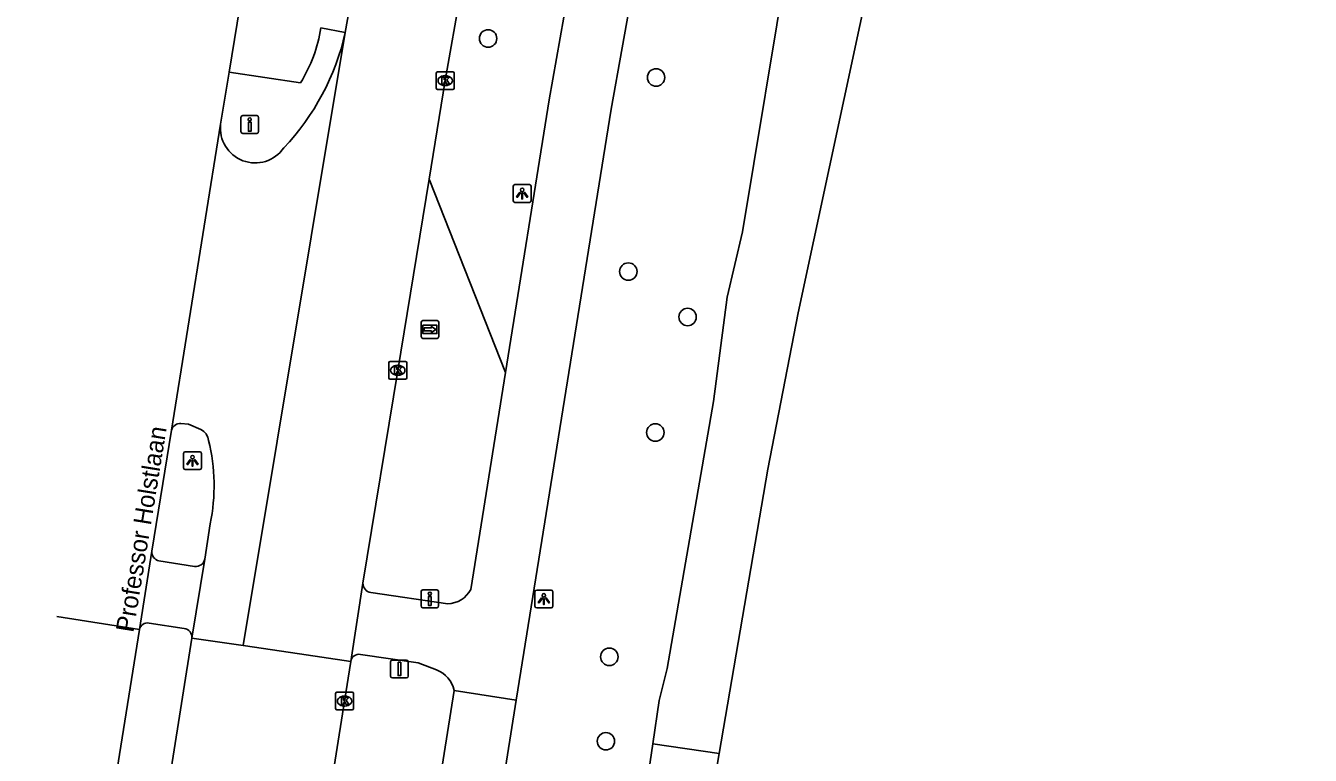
# Model space of a CAD drawing. Extents: x 160203 to 161526, y 379529 to 381797.
# Drawn here: x 160352.7 to 160424.8, y 380603.3 to 380644.2 of the extents above; entities that cross this region are included whole.
import ezdxf

# ---------------------------------------------------------------- set-up
doc = ezdxf.new("R2010")
doc.units = 0
for name, color, linetype in [('IMGEO_Berm_groen', 7, 'Continuous'), ('IMGEO_Boom', 7, 'Continuous'), ('IMGEO_Drukknoppaal', 7, 'Continuous'), ('IMGEO_Fietspad_gesloten', 7, 'Continuous'), ('IMGEO_Fietspad_open', 7, 'Continuous'), ('IMGEO_Grasland_agrarisch', 7, 'Continuous'), ('IMGEO_Kolk', 7, 'Continuous'), ('IMGEO_Lichtpunt', 7, 'Continuous'), ('IMGEO_Openbare_ruimte_label', 7, 'Continuous'), ('IMGEO_Rijbaan_regionaal_gesloten', 7, 'Continuous'), ('IMGEO_Verkeersbordpaal', 7, 'Continuous'), ('IMGEO_Verkeerseiland_open', 7, 'Continuous'), ('IMGEO_Waterloop', 7, 'Continuous'), ('IMGEO_Wegwijzer', 7, 'Continuous')]:
    doc.layers.add(name, color=color, linetype=linetype)

msp = doc.modelspace()

# ---------------------------------------------------------------- linework, layer by layer
at = {"layer": 'IMGEO_Berm_groen'}
for points in [[(160375.315, 380635.633), (160379.602, 380624.787)], [(160352.684, 380385.815), (160356.287, 380408.516), (160361.612, 380442.808), (160363.62, 380454.848), (160364.253, 380457.684), (160365.385, 380465.491), (160366.679, 380472.607), (160367.782, 380480.751), (160370.802, 380500), (160371.249, 380502.852), (160372.818, 380512.852), (160374.702, 380524.857), (160374.72, 380524.951), (160376.133, 380532.248), (160378.196, 380546.027), (160380.328, 380558.075), (160380.897, 380562.583), (160383.168, 380574.421), (160385.043, 380587.001), (160386.211, 380592.747), (160387.862, 380603.942)]]:
    msp.add_lwpolyline(points, dxfattribs=at)
at = {"layer": 'IMGEO_Boom'}
for centre in [(160378.626, 380643.518), (160388.05, 380641.33), (160386.493, 380630.443), (160389.817, 380627.893), (160388.006, 380621.413), (160385.426, 380608.831), (160385.234, 380604.095)]:
    msp.add_circle(centre, 0.489, dxfattribs=at)
at = {"layer": 'IMGEO_Drukknoppaal'}
for p, q in [((160364.857, 380639.19), (160365.647, 380639.19)), ((160365.647, 380639.19), (160364.857, 380639.19)), ((160364.757, 380638.29), (160364.757, 380639.09)), ((160364.757, 380639.09), (160364.757, 380638.29)), ((160365.747, 380639.09), (160365.747, 380638.29)), ((160365.747, 380638.29), (160365.747, 380639.09)), ((160365.647, 380638.19), (160364.857, 380638.19)), ((160364.857, 380638.19), (160365.647, 380638.19)), ((160374.961, 380612.585), (160375.751, 380612.585)), ((160375.751, 380612.585), (160374.961, 380612.585)), ((160374.861, 380611.685), (160374.861, 380612.485)), ((160374.861, 380612.485), (160374.861, 380611.685)), ((160375.851, 380612.485), (160375.851, 380611.685)), ((160375.851, 380611.685), (160375.851, 380612.485)), ((160375.751, 380611.585), (160374.961, 380611.585)), ((160374.961, 380611.585), (160375.751, 380611.585))]:
    msp.add_line(p, q, dxfattribs=at)
for points in [[(160365.327, 380638.815), (160365.327, 380638.315), (160365.177, 380638.315), (160365.177, 380638.815), (160365.327, 380638.815)], [(160375.431, 380612.21), (160375.431, 380611.71), (160375.281, 380611.71), (160375.281, 380612.21), (160375.431, 380612.21)]]:
    msp.add_lwpolyline(points, dxfattribs=at)
for centre in [(160365.252, 380638.98), (160375.356, 380612.375)]:
    msp.add_circle(centre, 0.085, dxfattribs=at)
for centre, start, end in [((160364.857, 380639.09), 90, 180), ((160364.857, 380639.09), 90, 180), ((160365.647, 380639.09), 0, 90), ((160365.647, 380639.09), 360, 90), ((160364.857, 380638.29), 180, 270), ((160364.857, 380638.29), 180, 270), ((160365.647, 380638.29), 270, 0), ((160365.647, 380638.29), 270, 0), ((160374.961, 380612.485), 90, 180), ((160374.961, 380612.485), 90, 180), ((160375.751, 380612.485), 0, 90), ((160375.751, 380612.485), 360, 90), ((160374.961, 380611.685), 180, 270), ((160374.961, 380611.685), 180, 270), ((160375.751, 380611.685), 270, 0), ((160375.751, 380611.685), 270, 0)]:
    msp.add_arc(centre, 0.1, start, end, dxfattribs=at)
at = {"layer": 'IMGEO_Fietspad_gesloten'}
for points in [[(160383.286, 380647.043), (160382.053, 380640.078), (160379.602, 380624.787)], [(160386.76, 380646.455), (160385.522, 380639.561), (160380.205, 380606.406)], [(160379.602, 380624.787), (160377.651, 380612.613)], [(160376.36, 380611.804), (160372.039, 380612.43)], [(160371.472, 380608.969), (160374.693, 380608.486), (160375.736, 380608.096)], [(160376.723, 380606.946), (160374.855, 380595.163)], [(160376.723, 380606.946), (160380.205, 380606.406)], [(160380.205, 380606.406), (160371.189, 380549.526), (160367.433, 380526.109), (160363.246, 380500), (160361.784, 380490.887), (160355.339, 380450.611)]]:
    msp.add_lwpolyline(points, dxfattribs=at)
for centre, radius, start, end in [((160372.143, 380612.961), 0.541, 179.27552, 258.89616), ((160376.321, 380613.301), 1.497, 271.49548, 332.65082), ((160371.397, 380608.49), 0.484, 81.13593, 170.17472), ((160375.175, 380606.616), 1.582, 12.026, 69.2504)]:
    msp.add_arc(centre, radius, start, end, dxfattribs=at)
at = {"layer": 'IMGEO_Fietspad_open'}
for points in [[(160360.16, 380614.208), (160362.159, 380613.9)], [(160361.581, 380610.416), (160359.604, 380610.72)]]:
    msp.add_lwpolyline(points, dxfattribs=at)
for centre, radius, start, end in [((160360.28, 380614.709), 0.515, 174.62319, 256.57055), ((160362.219, 380614.429), 0.532, 263.57434, 346.42303), ((160359.517, 380610.264), 0.464, 79.16832, 167.47411), ((160361.54, 380609.952), 0.466, 351.66885, 84.91148)]:
    msp.add_arc(centre, radius, start, end, dxfattribs=at)
at = {"layer": 'IMGEO_Grasland_agrarisch'}
msp.add_lwpolyline([(160391.591, 380603.409), (160387.523, 380579.574), (160379.296, 380526.737), (160378.851, 380524.294), (160377.634, 380517.623), (160376.818, 380512.224), (160375.308, 380502.238), (160374.97, 380500), (160372.848, 380488.626), (160370.146, 380472.104), (160369.369, 380465.742), (160366.989, 380450.176), (160364.586, 380436.343), (160363.043, 380425.732), (160361.825, 380419.072), (160360.362, 380409.1), (160358.765, 380400.008), (160356.87, 380389.591), (160356.183, 380385.289)], dxfattribs=at)
at = {"layer": 'IMGEO_Kolk'}
for p, q in [((160375.717, 380640.726), (160375.717, 380641.578)), ((160375.792, 380641.652), (160376.644, 380641.652)), ((160376.205, 380641.432), (160376.23, 380641.432)), ((160376.718, 380641.578), (160376.718, 380640.726)), ((160376.644, 380640.652), (160375.792, 380640.652)), ((160376.228, 380640.872), (160376.203, 380640.872)), ((160373.059, 380624.476), (160373.059, 380625.328)), ((160373.134, 380625.402), (160373.986, 380625.402)), ((160373.547, 380625.182), (160373.572, 380625.182)), ((160374.06, 380625.328), (160374.06, 380624.476)), ((160373.986, 380624.402), (160373.134, 380624.402)), ((160373.57, 380624.622), (160373.545, 380624.622)), ((160370.072, 380605.922), (160370.072, 380606.774)), ((160370.147, 380606.848), (160370.999, 380606.848)), ((160371.073, 380606.774), (160371.073, 380605.922)), ((160370.583, 380606.068), (160370.558, 380606.068)), ((160370.56, 380606.628), (160370.585, 380606.628)), ((160370.999, 380605.848), (160370.147, 380605.848))]:
    msp.add_line(p, q, dxfattribs=at)
for points in [[(160375.717, 380640.726), (160375.717, 380641.578)], [(160375.792, 380641.652), (160376.644, 380641.652)], [(160376.038, 380641.352), (160376.161, 380641.352), (160376.161, 380641.201), (160376.291, 380641.352), (160376.455, 380641.352), (160376.309, 380641.201), (160376.462, 380640.952), (160376.31, 380640.952), (160376.225, 380641.116), (160376.161, 380641.049), (160376.161, 380640.952), (160376.038, 380640.952), (160376.038, 380641.352)], [(160376.718, 380641.578), (160376.718, 380640.726)], [(160376.644, 380640.652), (160375.792, 380640.652)], [(160373.059, 380624.476), (160373.059, 380625.328)], [(160373.134, 380625.402), (160373.986, 380625.402)], [(160373.38, 380625.102), (160373.503, 380625.102), (160373.503, 380624.951), (160373.633, 380625.102), (160373.797, 380625.102), (160373.651, 380624.951), (160373.804, 380624.702), (160373.652, 380624.702), (160373.567, 380624.866), (160373.503, 380624.799), (160373.503, 380624.702), (160373.38, 380624.702), (160373.38, 380625.102)], [(160374.06, 380625.328), (160374.06, 380624.476)], [(160373.986, 380624.402), (160373.134, 380624.402)], [(160370.072, 380605.922), (160370.072, 380606.774)], [(160370.147, 380606.848), (160370.999, 380606.848)], [(160371.073, 380606.774), (160371.073, 380605.922)], [(160370.393, 380606.548), (160370.516, 380606.548), (160370.516, 380606.397), (160370.646, 380606.548), (160370.81, 380606.548), (160370.664, 380606.397), (160370.817, 380606.148), (160370.665, 380606.148), (160370.58, 380606.312), (160370.516, 380606.245), (160370.516, 380606.148), (160370.393, 380606.148), (160370.393, 380606.548)], [(160370.999, 380605.848), (160370.147, 380605.848)]]:
    msp.add_lwpolyline(points, dxfattribs=at)
for centre, start, end in [((160375.794, 380641.576), 91.55205, 178.44795), ((160375.794, 380641.576), 91.55205, 178.44795), ((160376.642, 380641.576), 1.55205, 88.44795), ((160376.642, 380641.576), 1.55205, 88.44795), ((160375.794, 380640.728), 181.55205, 268.44795), ((160375.794, 380640.728), 181.55205, 268.44795), ((160376.642, 380640.728), 271.55205, 358.44795), ((160376.642, 380640.728), 271.55205, 358.44795), ((160373.136, 380625.326), 91.55205, 178.44795), ((160373.136, 380625.326), 91.55205, 178.44795), ((160373.984, 380625.326), 1.55205, 88.44795), ((160373.984, 380625.326), 1.55205, 88.44795), ((160373.136, 380624.478), 181.55205, 268.44795), ((160373.136, 380624.478), 181.55205, 268.44795), ((160373.984, 380624.478), 271.55205, 358.44795), ((160373.984, 380624.478), 271.55205, 358.44795), ((160370.149, 380606.772), 91.55205, 178.44795), ((160370.149, 380606.772), 91.55205, 178.44795), ((160370.997, 380606.772), 1.55205, 88.44795), ((160370.997, 380606.772), 1.55205, 88.44795), ((160370.149, 380605.924), 181.55205, 268.44795), ((160370.149, 380605.924), 181.55205, 268.44795), ((160370.997, 380605.924), 271.55205, 358.44795), ((160370.997, 380605.924), 271.55205, 358.44795)]:
    msp.add_arc(centre, 0.0765, start, end, dxfattribs=at)
for centre, major_axis, ratio, start_param, end_param in [((160376.204, 380641.152), (-0.387, 0.002), 0.722429, 4.712389, 7.853982), ((160376.229, 380641.152), (-0.39, 0.002), 0.717154, 1.570796, 4.712389), ((160373.546, 380624.902), (-0.387, 0.002), 0.722429, 4.712389, 7.853982), ((160373.571, 380624.902), (-0.39, 0.002), 0.717154, 1.570796, 4.712389), ((160370.559, 380606.348), (-0.387, 0.002), 0.722429, 4.712389, 7.853982), ((160370.584, 380606.348), (-0.39, 0.002), 0.717154, 1.570796, 4.712389)]:
    msp.add_ellipse(centre, major_axis=major_axis, ratio=ratio, start_param=start_param, end_param=end_param, dxfattribs=at)
at = {"layer": 'IMGEO_Lichtpunt'}
for p, q in [((160380.038, 380635.224), (160380.038, 380634.417)), ((160380.038, 380635.224), (160380.038, 380634.417)), ((160380.94, 380635.319), (160380.132, 380635.319)), ((160380.94, 380635.319), (160380.132, 380635.319)), ((160381.034, 380634.417), (160381.034, 380635.224)), ((160381.034, 380634.417), (160381.034, 380635.224)), ((160380.132, 380634.323), (160380.94, 380634.323)), ((160380.132, 380634.323), (160380.94, 380634.323)), ((160361.544, 380620.235), (160361.544, 380619.428)), ((160361.544, 380620.235), (160361.544, 380619.428)), ((160362.446, 380620.33), (160361.638, 380620.33)), ((160362.446, 380620.33), (160361.638, 380620.33)), ((160362.54, 380619.428), (160362.54, 380620.235)), ((160362.54, 380619.428), (160362.54, 380620.235)), ((160361.638, 380619.334), (160362.446, 380619.334)), ((160361.638, 380619.334), (160362.446, 380619.334)), ((160382.158, 380612.573), (160381.35, 380612.573)), ((160382.158, 380612.573), (160381.35, 380612.573)), ((160381.256, 380612.478), (160381.256, 380611.671)), ((160381.256, 380612.478), (160381.256, 380611.671)), ((160382.252, 380611.671), (160382.252, 380612.478)), ((160382.252, 380611.671), (160382.252, 380612.478)), ((160381.35, 380611.577), (160382.158, 380611.577)), ((160381.35, 380611.577), (160382.158, 380611.577))]:
    msp.add_line(p, q, dxfattribs=at)
for points in [[(160380.412, 380634.888), (160380.451, 380634.86), (160380.263, 380634.598), (160380.225, 380634.625), (160380.412, 380634.888)], [(160380.514, 380634.84), (160380.561, 380634.84), (160380.561, 380634.518), (160380.514, 380634.518), (160380.514, 380634.84)], [(160380.624, 380634.86), (160380.662, 380634.887), (160380.849, 380634.625), (160380.81, 380634.597), (160380.624, 380634.86)], [(160361.918, 380619.899), (160361.957, 380619.871), (160361.769, 380619.609), (160361.731, 380619.636), (160361.918, 380619.899)], [(160362.02, 380619.851), (160362.067, 380619.851), (160362.067, 380619.529), (160362.02, 380619.529), (160362.02, 380619.851)], [(160362.13, 380619.871), (160362.168, 380619.898), (160362.355, 380619.636), (160362.316, 380619.608), (160362.13, 380619.871)], [(160381.63, 380612.142), (160381.669, 380612.114), (160381.481, 380611.852), (160381.443, 380611.879), (160381.63, 380612.142)], [(160381.732, 380612.094), (160381.779, 380612.094), (160381.779, 380611.772), (160381.732, 380611.772), (160381.732, 380612.094)], [(160381.842, 380612.114), (160381.88, 380612.141), (160382.067, 380611.879), (160382.028, 380611.851), (160381.842, 380612.114)]]:
    msp.add_lwpolyline(points, dxfattribs=at)
for centre in [(160380.537, 380635.022), (160362.043, 380620.033), (160381.755, 380612.276)]:
    msp.add_circle(centre, 0.0994, dxfattribs=at)
for centre, start, end in [((160380.132, 380635.224), 90, 180), ((160380.132, 380635.224), 90, 180), ((160380.94, 380635.224), 0, 90), ((160380.94, 380635.224), 0, 90), ((160380.132, 380634.417), 180, 270), ((160380.132, 380634.417), 180, 270), ((160380.94, 380634.417), 270, 0), ((160380.94, 380634.417), 270, 360), ((160361.638, 380620.235), 90, 180), ((160361.638, 380620.235), 90, 180), ((160362.446, 380620.235), 0, 90), ((160362.446, 380620.235), 0, 90), ((160361.638, 380619.428), 180, 270), ((160361.638, 380619.428), 180, 270), ((160362.446, 380619.428), 270, 0), ((160362.446, 380619.428), 270, 360), ((160381.35, 380612.478), 90, 180), ((160381.35, 380612.478), 90, 180), ((160382.158, 380612.478), 0, 90), ((160382.158, 380612.478), 0, 90), ((160381.35, 380611.671), 180, 270), ((160381.35, 380611.671), 180, 270), ((160382.158, 380611.671), 270, 0), ((160382.158, 380611.671), 270, 360)]:
    msp.add_arc(centre, 0.0946, start, end, dxfattribs=at)
at = {"layer": 'IMGEO_Rijbaan_regionaal_gesloten'}
for points in [[(160364.09, 380641.636), (160364.706, 380645.285), (160365.264, 380648.34)], [(160370.61, 380643.846), (160371.203, 380647.217)], [(160377.1, 380646.154), (160376.217, 380641.153), (160375.315, 380635.633)], [(160370.61, 380643.846), (160364.88, 380609.461)], [(160363.619, 380638.713), (160364.09, 380641.636)], [(160360.869, 380621.546), (160363.619, 380638.713)], [(160371.602, 380612.968), (160373.561, 380624.901), (160375.315, 380635.633)], [(160361.396, 380621.916), (160361.81, 380621.874), (160362.509, 380621.585)], [(160359.767, 380614.757), (160360.869, 380621.546)], [(160363.04, 380616.293), (160362.736, 380614.304)], [(160359.064, 380610.365), (160359.767, 380614.757)], [(160362.736, 380614.304), (160362.001, 380609.884)], [(160371.602, 380612.968), (160370.92, 380608.573)], [(160359.064, 380610.365), (160354.423, 380611.084)], [(160356.772, 380595.979), (160359.064, 380610.365)], [(160362.001, 380609.884), (160358.163, 380585.647)], [(160364.88, 380609.461), (160362.001, 380609.884)], [(160370.92, 380608.573), (160368.048, 380608.995), (160364.88, 380609.461)], [(160367.388, 380586.261), (160367.595, 380587.549), (160370.572, 380606.348), (160370.92, 380608.573)]]:
    msp.add_lwpolyline(points, dxfattribs=at)
for centre, radius, start, end in [((160357.193, 380646.845), 13.748, 316.47815, 347.39894), ((160365.557, 380638.487), 1.951, 173.35829, 325.34896), ((160361.333, 380621.446), 0.474, 82.33913, 167.80528), ((160362.128, 380620.854), 0.825, 7.90279, 62.50328), ((160352.516, 380618.417), 10.736, 348.58919, 13.73959)]:
    msp.add_arc(centre, radius, start, end, dxfattribs=at)
at = {"layer": 'IMGEO_Verkeersbordpaal'}
for p, q in [((160373.156, 380607.75), (160373.156, 380608.55)), ((160373.156, 380608.55), (160373.156, 380607.75)), ((160373.256, 380608.65), (160374.046, 380608.65)), ((160374.046, 380608.65), (160373.256, 380608.65)), ((160374.146, 380608.55), (160374.146, 380607.75)), ((160374.146, 380607.75), (160374.146, 380608.55)), ((160374.046, 380607.65), (160373.256, 380607.65)), ((160373.256, 380607.65), (160374.046, 380607.65))]:
    msp.add_line(p, q, dxfattribs=at)
msp.add_lwpolyline([(160373.576, 380608.525), (160373.726, 380608.525), (160373.726, 380607.775), (160373.576, 380607.775), (160373.576, 380608.525)], dxfattribs=at)
for centre, start, end in [((160373.256, 380608.55), 90, 180), ((160373.256, 380608.55), 90, 180), ((160374.046, 380608.55), 0, 90), ((160374.046, 380608.55), 360, 90), ((160373.256, 380607.75), 180, 270), ((160373.256, 380607.75), 180, 270), ((160374.046, 380607.75), 270, 0), ((160374.046, 380607.75), 270, 0)]:
    msp.add_arc(centre, 0.1, start, end, dxfattribs=at)
at = {"layer": 'IMGEO_Verkeerseiland_open'}
for points in [[(160369.244, 380644.107), (160370.61, 380643.846)], [(160364.09, 380641.636), (160368.101, 380641.026)]]:
    msp.add_lwpolyline(points, dxfattribs=at)
msp.add_arc((160361.073, 380645.386), 8.271, 328.18726, 351.1047, dxfattribs=at)
at = {"layer": 'IMGEO_Waterloop'}
for points in [[(160424.751, 380748.622), (160421.704, 380738.223), (160400.367, 380648.355), (160396.021, 380628.131), (160394.312, 380619.353), (160391.591, 380603.409)], [(160387.862, 380603.942), (160388.223, 380606.389), (160388.675, 380608.166), (160391.266, 380623.144), (160392.046, 380629.012), (160392.89, 380632.678), (160395.463, 380648.127), (160395.831, 380649.266), (160397.982, 380660.047), (160413.118, 380722.694), (160414.318, 380728.603)], [(160391.591, 380603.409), (160387.862, 380603.942)]]:
    msp.add_lwpolyline(points, dxfattribs=at)
at = {"layer": 'IMGEO_Wegwijzer'}
for p, q in [((160374.969, 380627.696), (160375.759, 380627.696)), ((160375.759, 380627.696), (160374.969, 380627.696)), ((160374.869, 380626.796), (160374.869, 380627.596)), ((160374.869, 380627.596), (160374.869, 380626.796)), ((160375.859, 380627.596), (160375.859, 380626.796)), ((160375.859, 380626.796), (160375.859, 380627.596)), ((160375.759, 380626.696), (160374.969, 380626.696)), ((160374.969, 380626.696), (160375.759, 380626.696))]:
    msp.add_line(p, q, dxfattribs=at)
for points in [[(160374.97, 380627.428), (160375.758, 380627.428), (160375.758, 380626.964), (160374.97, 380626.964), (160374.97, 380627.428)], [(160375.035, 380627.28), (160375.035, 380627.196), (160375.035, 380627.112), (160375.446, 380627.112), (160375.446, 380627.029), (160375.693, 380627.196), (160375.446, 380627.363), (160375.446, 380627.28), (160375.035, 380627.28)]]:
    msp.add_lwpolyline(points, dxfattribs=at)
for centre, start, end in [((160374.969, 380627.596), 90, 180), ((160374.969, 380627.596), 90, 180), ((160375.759, 380627.596), 0, 90), ((160375.759, 380627.596), 360, 90), ((160374.969, 380626.796), 180, 270), ((160374.969, 380626.796), 180, 270), ((160375.759, 380626.796), 270, 0), ((160375.759, 380626.796), 270, 0)]:
    msp.add_arc(centre, 0.1, start, end, dxfattribs=at)

# ---------------------------------------------------------------- texts
at = {"layer": 'IMGEO_Openbare_ruimte_label'}
msp.add_text('Professor Holstlaan', height=1, rotation=80.73548, dxfattribs=at).set_placement((160358.721, 380610.158))

doc.saveas('drawing.dxf')
